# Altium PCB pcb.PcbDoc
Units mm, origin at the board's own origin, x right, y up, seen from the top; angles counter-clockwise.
Board outline 37.4 x 38.1 mm, 2 copper layers (Top Layer, Bottom Layer); 122 components, 90 nets, 413 pads, 142 vias.
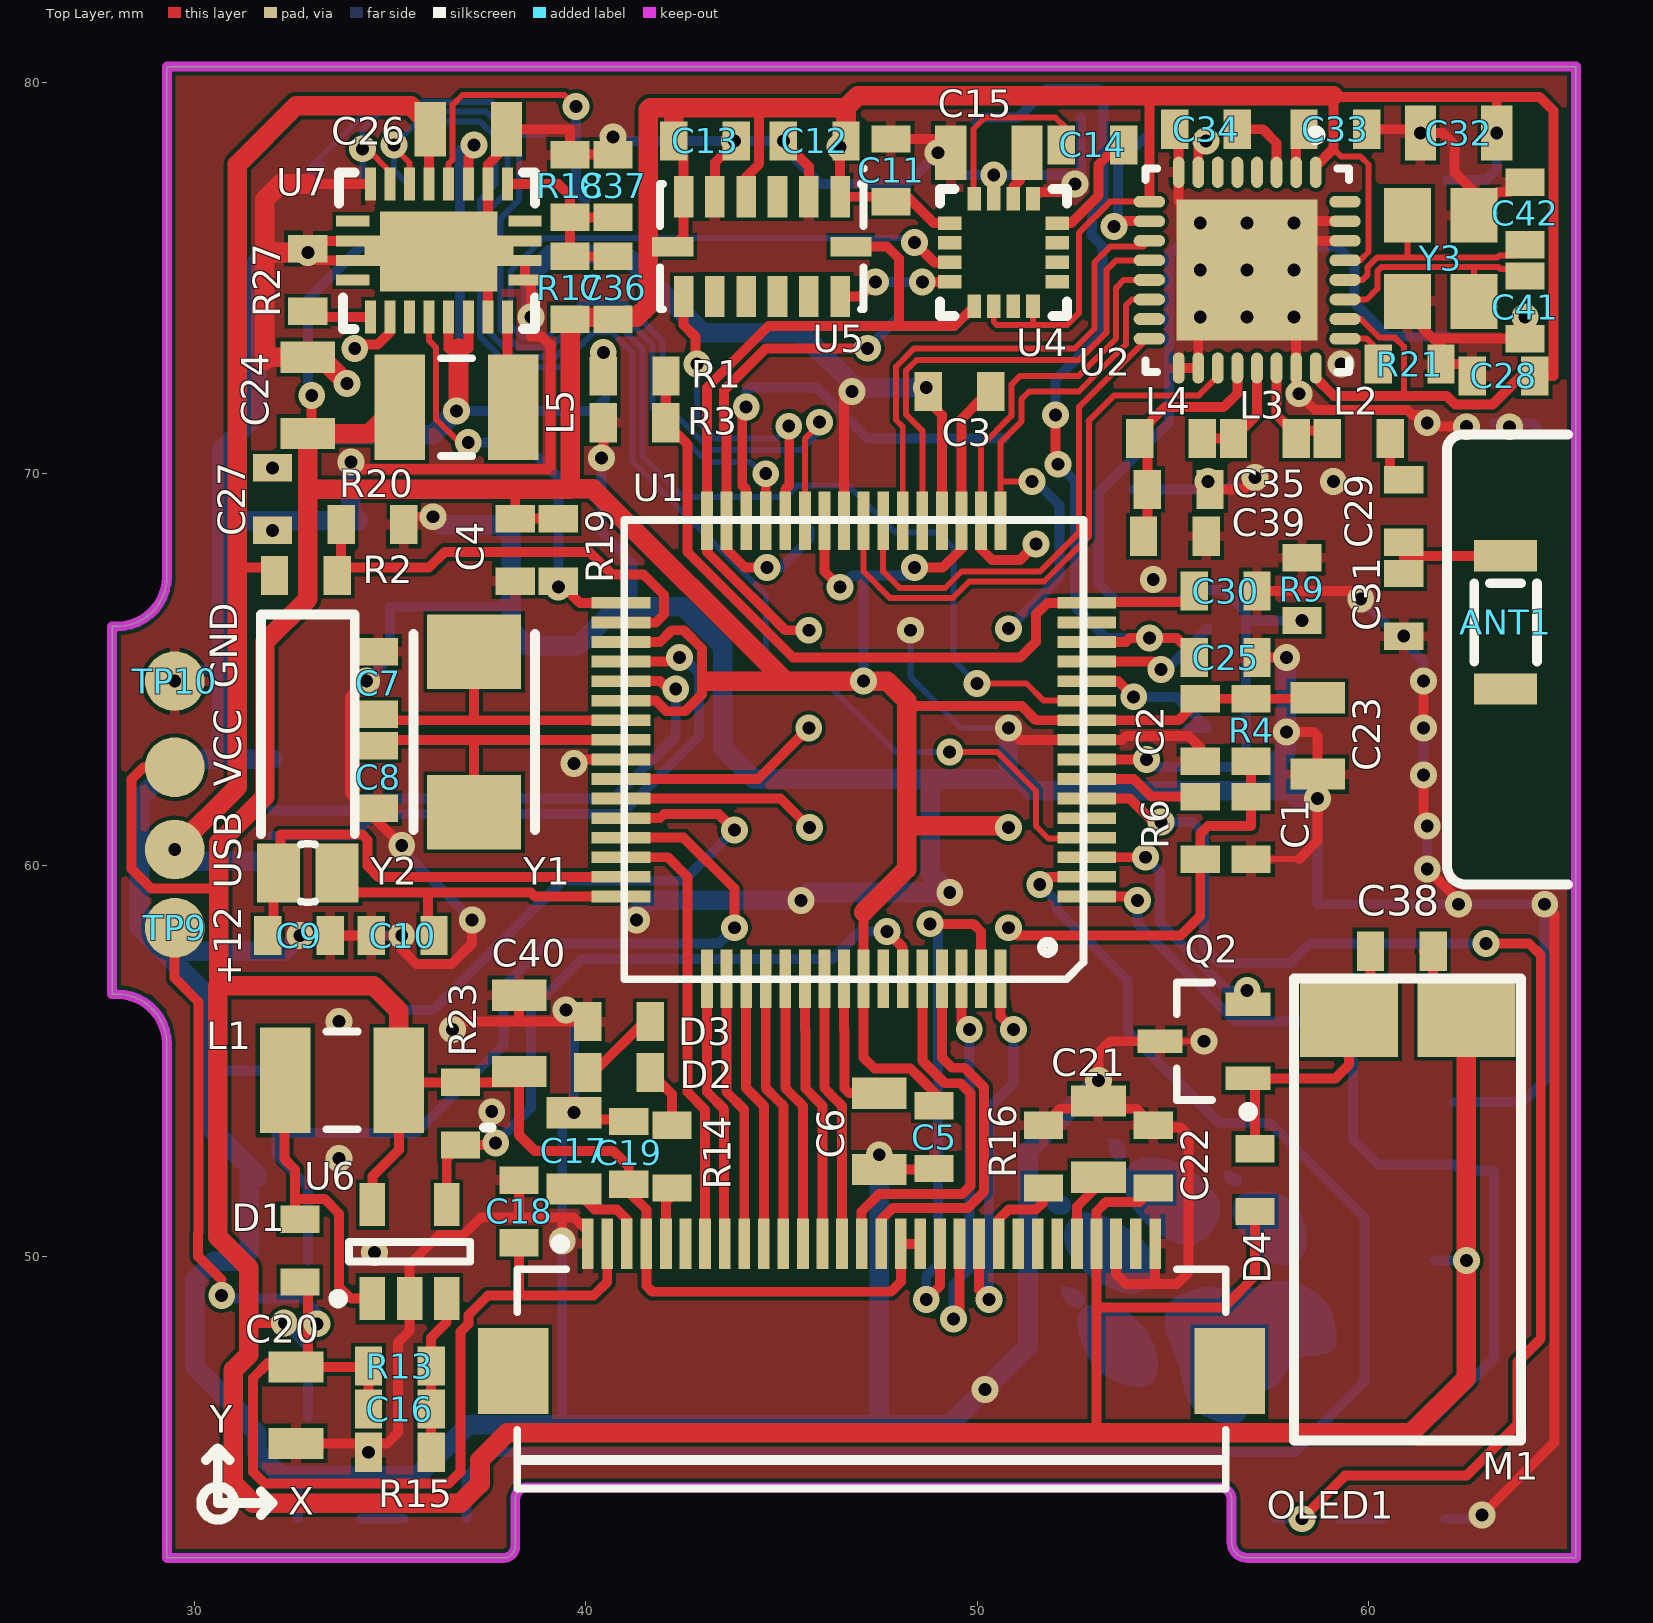
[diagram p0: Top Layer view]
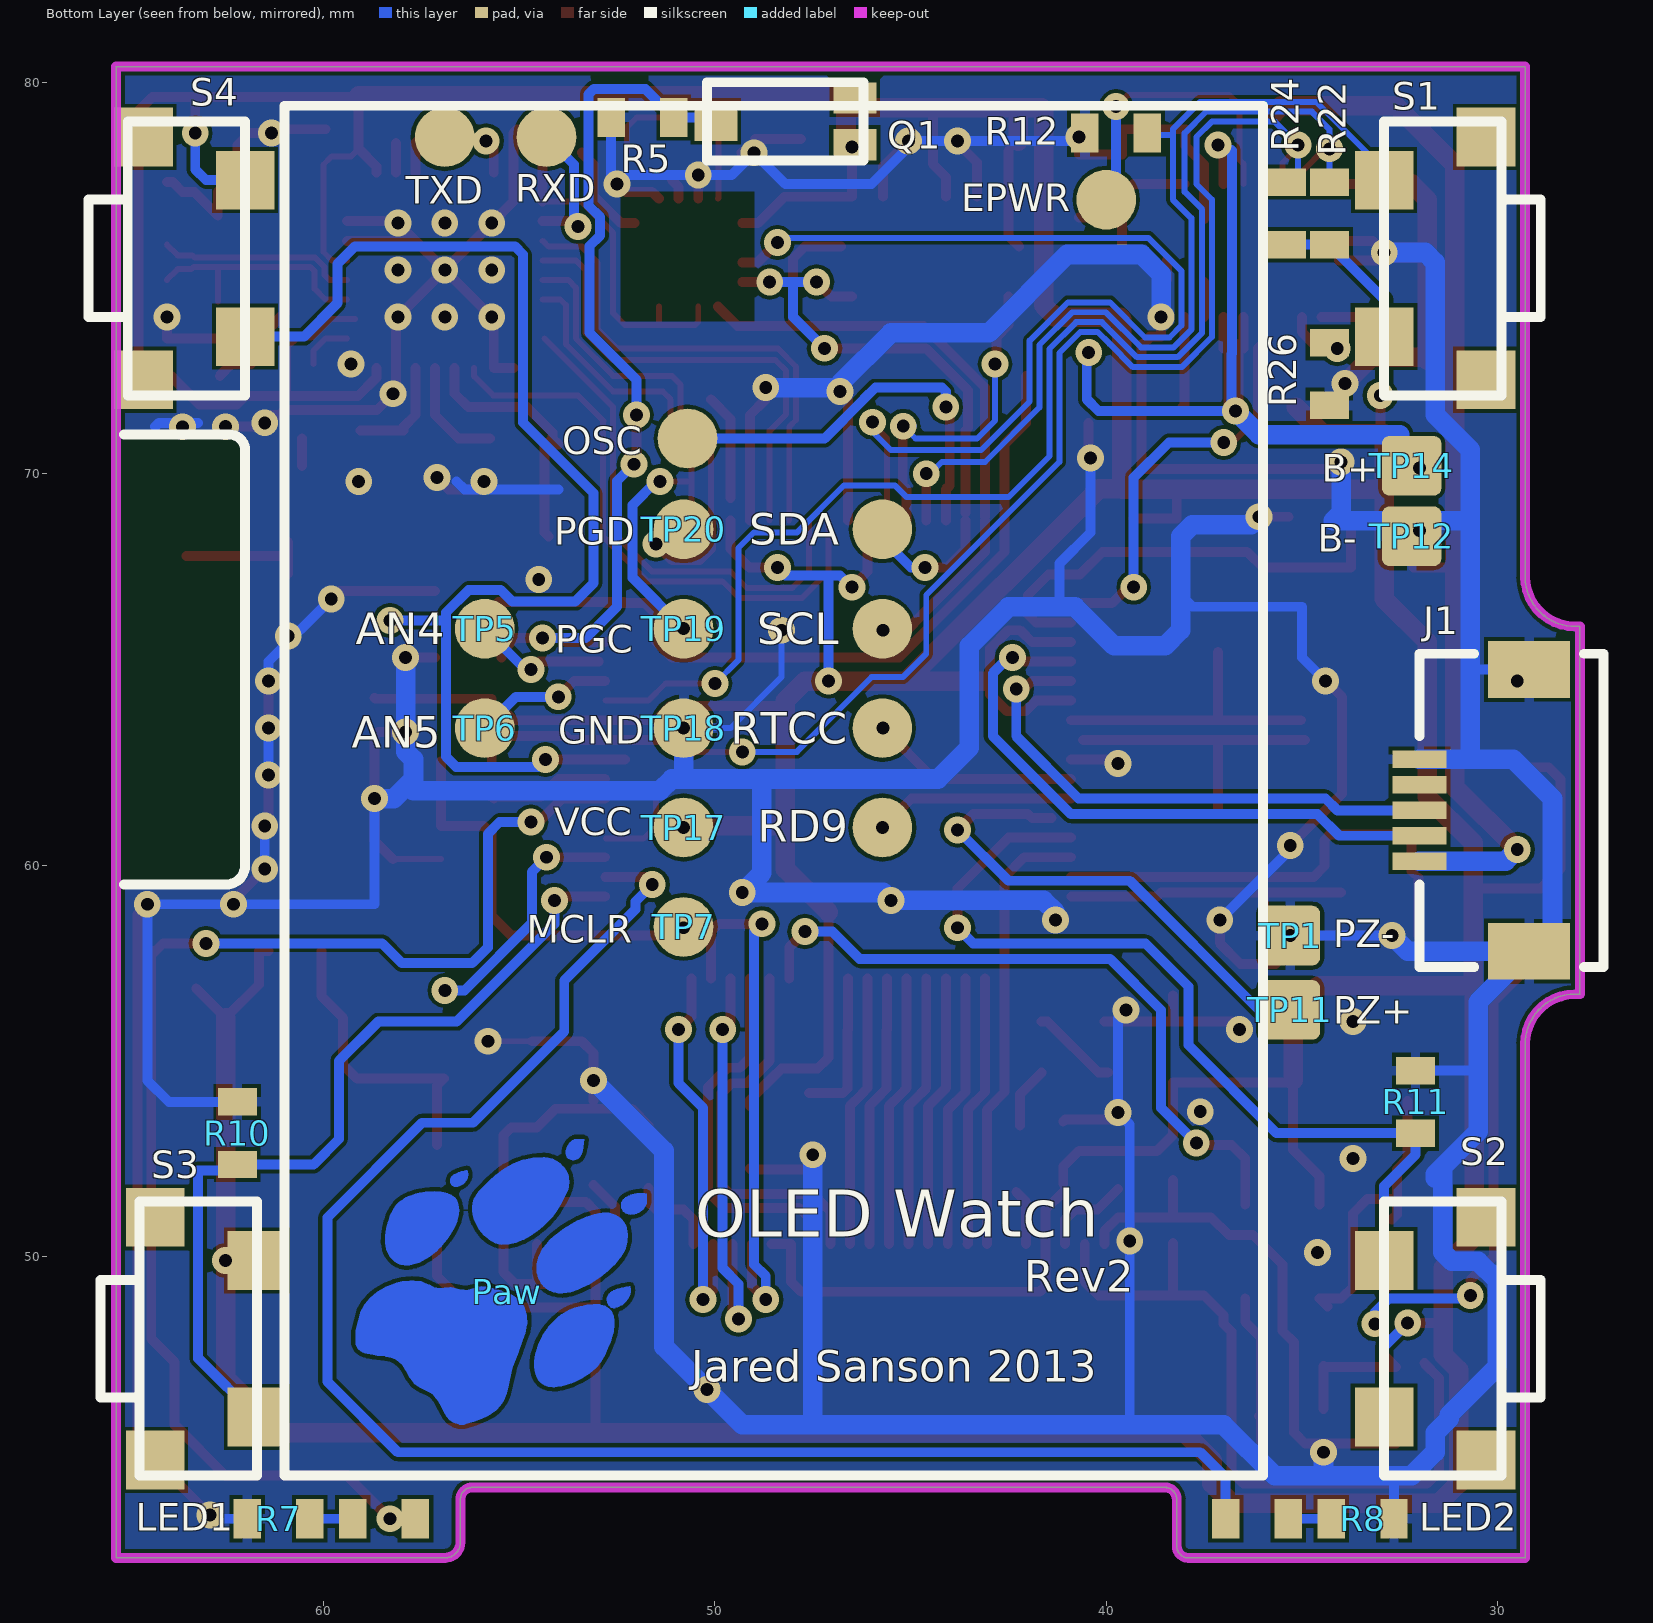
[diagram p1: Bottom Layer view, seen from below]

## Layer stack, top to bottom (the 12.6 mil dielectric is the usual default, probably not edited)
Top Layer: signal copper 0.0356
Dielectric: dielectric 0.32, FR-4, Dk 4.8
Bottom Layer: signal copper 0.0356

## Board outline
56.9,42.3 cw(c56.9,42.7) 56.5,42.7 56.5,43.8 ccw(c56.2,43.8) 56.2,44.1 38.5,44.1 ccw(c38.5,43.8) 38.2,43.8 38.2,42.6 cw(c37.9,42.6) 37.9,42.3 29.3,42.3 29.3,55.43 ccw(c28.03,55.43) 28.03,56.7 27.9,56.7 27.9,66.1 28.03,66.1 ccw(c28.03,67.37) 29.3,67.37 29.3,80.4 65.3,80.4 65.3,42.3

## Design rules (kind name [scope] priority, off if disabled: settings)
Clearance [All] p1: gap=0.1
HoleSize [All] p1: absolutevalues=TRUE maxlimit=2.54 minlimit=0.33 maxpercent=80.000 minpercent=20.000
MaxMinImpedance [InNet('ANT')] p1: minimum=50.00 maximum=50.00
MinimumAnnularRing [All] p1: minimumring=0.178
MinimumSolderMaskSliver [All] p1: minsoldermaskwidth=0
NetAntennae ANT_Antennae [InNet('ANT')] p1: netantennaetolerance=100
NetAntennae [All] p2: netantennaetolerance=0
PolygonConnect PolygonConnect_U2 [All vs (ObjectKind = 'Pad') And (Name = 'U2-33')] p1: connectstyle=Direct reliefconductorwidth=0.254 reliefentries=4 polygonreliefangle="90 Angle"
PolygonConnect PolygonConnect_Via [All vs ObjectKind='Via'] p2: connectstyle=Direct reliefconductorwidth=0.254 reliefentries=4 polygonreliefangle="90 Angle"
PolygonConnect [All] p3: connectstyle=Relief reliefconductorwidth=0.254 reliefentries=4 polygonreliefangle="90 Angle"
RoutingVias [All] p1: holewidth=0.508 width=0.686 viastyle="Through Hole" minholewidth=0.33 minwidth=0.686 maxholewidth=0.711 maxwidth=0.686
SilkscreenOverComponentPads [All] p1: minsilkscreentomaskgap=0.254
SolderMaskExpansion [All] p1: expansion=0.01
Width [All] p1: maxlimit=0.5 minlimit=0.152 preferedwidth=0.254
24 further rules are at their usual default settings.

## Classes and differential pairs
component class sensors: 0.7 C11 C12 C13 C14 C15 C25 Q1 R5 U4 U5
component class power: C24 C26 C27 C36 C37 EPWR J1 L5 R17 R18 R19 R22 R24 R26 R27 TP10 TP12 TP14 U7 U8 USB VCC
component class oled: 0.7 C16 C17 C18 C19 C20 C21 C22 C40 D1 D2 D3 L1 OLED1 R13 R14 R15 R16 R23 TP9 U6
component class cpu: C1 C2 C3 C4 C5 C6 C7 C8 C9 C10 C23 C30 C38 D4 LED1 LED2 M1 OSC Q2 R1 R2 R3 R4 R6 R7 R8 R9 R10 R11 R12 R20 RD9 RTCC S1 S2 S3 S4 SCL SDA TP1 TP5 TP6 TP7 TP11 TP17 TP18 TP19 TP20 U1 Y1 Y2
component class bluetoothle: ANT1 C28 C29 C31 C32 C33 C34 C35 C39 C41 C42 L2 L3 L4 R21 RXD TXD U2 Y3

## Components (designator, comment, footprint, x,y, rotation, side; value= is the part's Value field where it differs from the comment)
ANT1 "2.4GHz Chip Antenna" 2450AT18A100E 63.5,67.9 r270 top
C1 "Cap" 0603C 57,61.6 r270 top
C2 "Cap" 0603C 55.7,64.1 r270 top
C3 "Cap" 0603C 50.2,72.1 r180 top
C4 "Cap" 0603C 38.2,68.7 r270 top
C5 "Cap" 0603C 48.9,53.7 r270 top
C6 "Cap" 0805C 47.5,54.2 r270 top
C7 "Cap" 0603C 34.7,64 r90 top
C8 "Cap" 0603C 34.7,62.9 r270 top
C9 "Cap" 0603C 32.025,58.2 r0 top
C10 "Cap" 0603C 35.975,58.2 r180 top
C11 "Cap" 0603C 47.8,77.1 r90 top
C12 "Cap" 0603C 46.5,78.5 r180 top
C13 "Cap" 0603C 42.4,78.5 r0 top
C14 "Cap" 0603C 52.3,78.4 r0 top
C15 "Cap Pol1" 0805C 51.3,78.2 r180 top
C16 "Cap" 0603C 34.6,46.1 r0 top
C17 "Tantalum" 0805C 39.7,51.7 r90 top
C18 "Cap" 0603C 38.3,50.5 r90 top
C19 "Cap" 0603C 41.1,52 r90 top
C20 "Cap" 0805C 32.6,47.2 r270 top
C21 "Cap" 0805C 53.1,52 r90 top
C22 "Cap" 0603C 54.5,51.9 r90 top
C23 "Cap" 0805C 58.7,64.3 r270 top
C24 "Cap" 0805C 32.9,71 r90 top
C25 "Cap" 0603C 55.7,65.3 r0 top
C26 "Cap" 0805C 36,78.8 r0 top
C27 "Cap" 0603C 32,70 r270 top
C28 "Cap" 0603C 62.8,72.5 r0 top
C29 "Cap" 0603C 60.9,69.7 r270 top
C30 "Cap" 0603C 55.7,67 r0 top
C31 "Cap" 0603C 60.9,66 r90 top
C32 "Cap" 0805C 63.3,78.7 r180 top
C33 "Cap" 0603C 58.5,78.8 r0 top
C34 "Cap" 0603C 56.5,78.8 r180 top
C35 "Cap" 0603C 54.5,69.6 r0 top
C36 "Cap" 0603C 40.7,74.1 r90 top
C37 "Cap" 0603C 40.7,76.7 r90 top
C38 "Cap" 0603C 61.5,57.8 r180 top
C39 "Cap" 0603C 54.4,68.4 r0 top
C40 "Cap" 0805C 38.3,54.7 r90 top
C41 "Cap" 0603C 64,73.6 r90 top
C42 "Cap" 0603C 64,76 r90 top
D1 "MBR0520" 0603D 32.7,50.8 r270 top
D2 "1N4148" 0603D 41.5,54.7 r180 top
D3 "1N4148" 0603D 41.5,56 r180 top
D4 "1N4148" 0603D 57.1,52.6 r270 top
EPWR "AC" TESTPOINT_TOP#1 40,77 r90 bottom (schematic designator TP3)
J1 "MicroUSB" MICRO_USB 32,62.7 r180 bottom
L1 "Inductor" INDC3225N 33.775,54.5 r180 top
L2 "Inductor" 0603L 59.1,70.9 r0 top
L3 "Inductor" 0603L 56.7,70.9 r0 top
L4 "Inductor" 0603L 55.6,70.9 r180 top
L5 "Inductor" INDC3225N 36.7,71.7 r180 top
LED1 "Green" 0603LED 57.8,43.3 r0 bottom
LED2 "Blue" 0603LED 36.8,43.3 r180 bottom
M1 "Vibration Motor" VIBRATION_MOTOR 61,57.3 r270 top
OLED1 "NL128128C OLED" FFC/SM0.5-2H30 47.3,48.7 r0 top
OSC "16MHz" TESTPOINT_TOP#1 50.7,70.9 r90 bottom (schematic designator TP2)
Paw "Comment" PAWPRINT 55.3,49.1 r0 bottom
Q1 "Photo NPN" TEMT6000 46.2,78 r0 bottom
Q2 "MOSFET-N" SOT-23B_N 55.8,55.5 r180 top
R1 "Res3" 0603R 40.6,72.5 r0 top
R2 "Res3" 0603R 33.5,67.4 r180 top
R3 "Res3" 0603R 41.9,71.3 r180 top
R4 "Res3" 0603R 57,64.1 r270 top
R5 "Res3" 0603R 51.2,79.1 r0 bottom
R6 "Res3" 0603R 55.7,60.3 r90 top
R7 "Res3" 0603R 61.8,43.3 r180 bottom
R8 "Res3" 0603R 32.8,43.3 r0 bottom
R9 "Res3" 0603R 58.3,66.4 r90 top
R10 "Res3" 0603R 62.2,52.5 r90 bottom
R11 "Res3" 0603R 32.1,53.3 r90 bottom
R12 "Res3" 0603R 39.1,78.7 r0 bottom
R13 "Res3" 0603R 35.9,47.2 r180 top
R14 "Res3" 0603R 42.2,53.2 r270 top
R15 "Res3" 0603R 34.6,45 r0 top
R16 "Res3" 0603R 51.7,51.9 r90 top
R17 "Res3" 0603R 39.6,74.1 r90 top
R18 "Res3" 0603R 39.6,76.7 r90 top
R19 "Res3" 0603R 39.3,68.7 r270 top
R20 "Res3" 0603R 35.2,68.7 r180 top
R21 "Res3" 0603R 61.7,72.8 r180 top
R22 "Res3" 0603R 34.3,76 r90 bottom
R23 "Res3" 0603R 36.8,53 r90 top
R24 "Res3" 0603R 35.4,76 r90 bottom
R26 "Res3" 0603R 34.3,73.2 r270 bottom
R27 "Res3" 0603R 32.9,74.3 r90 top
RD9 "" TESTPOINT_TOP#1 45.72,60.96 r90 bottom (schematic designator TP2)
RTCC "RTCC" TESTPOINT_TOP#1 45.72,63.5 r90 bottom (schematic designator TP8)
RXD "AN4" TESTPOINT_TOP#1 54.3,78.6 r90 bottom (schematic designator TP4)
S1 "SideButton" SIDE_BUTTON 32.9,79 r180 bottom
S2 "SideButton" SIDE_BUTTON 32.9,51.4 r180 bottom
S3 "SideButton" SIDE_BUTTON 61.7,44.4 r0 bottom
S4 "SideButton" SIDE_BUTTON 62,72 r0 bottom
SCL "SCL" TESTPOINT_TOP#1 45.72,66.04 r90 bottom (schematic designator TP3)
SDA "SDA" TESTPOINT_TOP#1 45.72,68.58 r90 bottom (schematic designator TP2)
TP1 "PZ-" TESTPOINT_TOP#2 35.3,58.2 r180 bottom
TP5 "AN4" TESTPOINT_TOP#1 55.88,66.04 r90 bottom
TP6 "AN5" TESTPOINT_TOP#1 55.88,63.5 r90 bottom
TP7 "MCLR" TESTPOINT_TOP#1 50.8,58.42 r90 bottom
TP9 "+12" TESTPOINT_TOP#1 29.5,58.4 r90 top
TP10 "GND" TESTPOINT_TOP#1 29.5,64.7 r90 top
TP11 "PZ+" TESTPOINT_TOP#2 35.3,56.3 r90 bottom
TP12 "B-" TESTPOINT_TOP#2 32.2,68.4 r90 bottom
TP14 "B+" TESTPOINT_TOP#2 32.2,70.2 r90 bottom
TP17 "VCC" TESTPOINT_TOP#1 50.8,60.96 r0 bottom
TP18 "GND" TESTPOINT_TOP#1 50.8,63.5 r0 bottom
TP19 "PGC" TESTPOINT_TOP#1 50.8,66.04 r0 bottom
TP20 "PGD" TESTPOINT_TOP#1 50.8,68.58 r90 bottom
TXD "AN4" TESTPOINT_TOP#1 56.9,78.6 r90 bottom (schematic designator TP3)
U1 "PIC24FJ128GB206" TQFP_64_10MM 54,59.2 r180 top
U2 "nRF8001" QFN50P500X500-32V5N 56.9,75.2 r270 top
U4 "HMC5883L" HMC5883L_16PINQFN 49.3,74.9 r90 top
U5 "MMA7455LR1" LGA80P500X300-14N 44.5,75.8 r270 top
U6 "LM27313XMF" MF05A_N 35.5,50.125 r90 top
U7 "BQ25010" RHL 38,77.4 r180 top
USB "VBUS" TESTPOINT_TOP#1 29.5,60.4 r90 top (schematic designator TP8)
VCC "VCC" TESTPOINT_TOP#1 29.5,62.5 r90 top (schematic designator TP4)
Y1 "32MHz" ABRACON32MHZ 37.2,65.5 r270 top
Y2 "32.768kHz" BCY-W2/D1.5 32.9,59.8 r270 top
Y3 "TXC-16MHz" TXC-16MHZ 62.7,76.6 r270 top

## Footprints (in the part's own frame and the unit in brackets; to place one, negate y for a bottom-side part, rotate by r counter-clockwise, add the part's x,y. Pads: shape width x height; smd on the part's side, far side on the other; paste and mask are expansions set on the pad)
0603C [mm] "0603 (1608 metric) Capacitor Footprint"
  rect 0.7x1 smd mask+0.01: 1(-0.15,0) 2(1.45,0)
  body extent -0.15,-0.4 1.45,0.4, height 0.8
0603D [mm] "0603 (1608 metric) Diode Footprint"
  rect 0.7x1 smd mask+0.01: 1(-0.15,0) 2(1.45,0)
  body extent -0.12,-0.4 1.43,0.4, height 0.63
0603L [mm] "0603 (1608 metric) Inductor Footprint"
  rect 0.7x1 smd mask+0.01: 1(-0.15,0) 2(1.45,0)
  body extent -0.15,-0.4 1.45,0.4, height 0.8
0603LED [mm] "0603 (1608 metric) LED Footprint"
  rect 0.7x1 smd mask+0.01: 1(-0.15,0) 2(1.45,0)
  body extent -0.12,-0.37 1.43,0.38, height 0.55
0603R [mm] "0603 (1608 metric) Resistor Footprint"
  rect 0.7x1 smd mask+0.01: 1(-0.15,0) 2(1.45,0)
  body extent -0.15,-0.4 1.45,0.4, height 0.45
0805C [mm] "0805 (2012 metric) Capacitor Footprint"
  rect 0.8x1.4 smd mask+0.01: 1(0.025,0) 2(1.975,0)
  body extent 0,-0.63 2,0.63, height 1.1
2450AT18A100E [mm] "2.4GHz Chip Antenna"
  rect 0.8x1.6 smd: 1(0,0) 2(3.4,0)
  silkscreen extent 0.7,-0.8 2.7,0.8, body extent 0.1,-0.8 3.3,0.8, height 1.33
ABRACON32MHZ [mm] "ABRACON 32MHz SMD Crystal"
  rect 1.9x2.4 smd: 1(0.05,-0.05) 2(4.15,-0.05)
  silkscreen extent -0.4,-1.6 4.6,1.5, body extent -0.4,-1.65 4.6,1.55, height 1.3
BCY-W2/D1.5 [mm] "Crystal, Thru-Hole; 2 Leads; Body 1.5 x 5.1 mm (Dia.xH)"
  rect 1.5x1.1 smd: 1(0,0.75) 2(0,-0.75)
  silkscreen extent -0.75,-0.18 0.75,0.18
FFC/SM0.5-2H30 [mm] "Connector; FH12 Series; 30 Position; 0.5mm Spaced Bottom Contact"
  rect 0.3x1.3 smd: 1(-7.25,1.625) 2(-6.75,1.625) 3(-6.25,1.625) 4(-5.75,1.625) 5(-5.25,1.625) 6(-4.75,1.625) 7(-4.25,1.625) 8(-3.75,1.625) 9(-3.25,1.625) 10(-2.75,1.625) 11(-2.25,1.625) 12(-1.75,1.625) 13(-1.25,1.625) 14(-0.75,1.625) 15(-0.25,1.625) 16(0.25,1.625) 17(0.75,1.625) 18(1.25,1.625) 19(1.75,1.625) 20(2.25,1.625) 21(2.75,1.625) 22(3.25,1.625) 23(3.75,1.625) 24(4.25,1.625) 25(4.75,1.625) 26(5.25,1.625) 27(5.75,1.625) 28(6.25,1.625) 29(6.75,1.625) 30(7.25,1.625)
  rect 1.8x2.2 smd: 31(-9.15,-1.625) 32(9.15,-1.625)
  silkscreen extent -9.05,-4.62 9.05,1.75, body extent -9.05,-4.62 9.05,0.97, height 2
HMC5883L_16PINQFN [mm]
  rect 0.6x0.35 smd: 1(-0.625,-0.625) 2(-0.625,-1.125) 3(-0.625,-1.625) 4(-0.625,-2.125) 9(2.125,-2.125) 10(2.125,-1.625) 11(2.125,-1.125) 12(2.125,-0.625)
  rect 0.35x0.6 smd: 5(0,-2.75) 6(0.5,-2.75) 7(1,-2.75) 8(1.5,-2.75) 13(1.5,0) 14(1,0) 15(0.5,0) 16(0,0)
  silkscreen extent -0.87,-3 2.37,0.25, body extent -0.75,-2.87 2.25,0.13, height 0.9
INDC3225N [mm] "Chip Inductor, Body 3.2x2.5mm, IPC Medium Density"
  rect 1.3x2.7 smd: 1(-1.45,0) 2(1.45,0)
  silkscreen extent -0.4,-1.25 0.4,1.25, body extent -1.7,-1.35 1.7,1.35, height 1.5
LGA80P500X300-14N [mm] "LGA, 14-Leads, Body 3x5x0.92mm, Pitch 0.8mm, IPC Medium Density"
  rect 1.05x0.5 smd: 1(-1.275,2) 2(-1.275,1.2) 3(-1.275,0.4) 4(-1.275,-0.4) 5(-1.275,-1.2) 6(-1.275,-2) 8(1.275,-2) 9(1.275,-1.2) 10(1.275,-0.4) 11(1.275,0.4) 12(1.275,1.2) 13(1.275,2)
  rect 0.5x1.05 smd: 7(0,-2.275) 14(0,2.275)
  silkscreen extent -2.05,-2.6 1.6,2.65, body extent -1.57,-2.57 1.58,2.58, height 1
MF05A_N [mm] "SOT23, 5-Leads, Body 2.9x1.6mm, Pitch 0.95mm, Lead Span 2.8mm, IPC Medium Density"
  rect 1.1x0.65 smd: 1(-1.2,0.95) 2(-1.2,0) 3(-1.2,-0.95) 4(1.2,-0.95) 5(1.2,0.95)
  silkscreen extent -1.32,-1.55 0.25,1.95, body extent -0.9,-1.55 0.9,1.55, height 1.19
MICRO_USB [mm] "Micro USB Connector"
  rect 1.38x0.45 smd: 1(0,-2.6) 2(0,-1.95) 3(0,-1.3) 4(0,-0.65) 5(0,0)
  rect 2.1x1.45 smd: 5(2.8,-4.9) 5(2.8,2.3)
  silkscreen extent 0,-5.3 4.7,2.7, body extent 0.05,-5.29 5.48,2.69, height 2.69
PAWPRINT [mm] "Wolf Paw"
  Top Layer drawing of 732 lines, arcs and shapes, not listed
QFN50P500X500-32V5N [mm] "QFN, 32-Leads, Body 5x5mm, Pitch 0.5mm, IPC Medium Density"
  oval 0.8x0.3 smd: 1(-2.5,1.75) 2(-2.5,1.25) 3(-2.5,0.75) 4(-2.5,0.25) 5(-2.5,-0.25) 6(-2.5,-0.75) 7(-2.5,-1.25) 8(-2.5,-1.75) 17(2.5,-1.75) 18(2.5,-1.25) 19(2.5,-0.75) 20(2.5,-0.25) 21(2.5,0.25) 22(2.5,0.75) 23(2.5,1.25) 24(2.5,1.75)
  oval 0.3x0.8 smd: 9(-1.75,-2.5) 10(-1.25,-2.5) 11(-0.75,-2.5) 12(-0.25,-2.5) 13(0.25,-2.5) 14(0.75,-2.5) 15(1.25,-2.5) 16(1.75,-2.5) 25(1.75,2.5) 26(1.25,2.5) 27(0.75,2.5) 28(0.25,2.5) 29(-0.25,2.5) 30(-0.75,2.5) 31(-1.25,2.5) 32(-1.75,2.5)
  rect 3.6x3.6 smd: 33(0,0)
  silkscreen extent -3.57,-2.6 2.6,2.6, body extent -2.58,-2.58 2.58,2.58, height 1
RHL [mm]
  rect 0.85x0.28 smd mask+0.07: 0(-0.45,1.95) 0(-0.45,1.45) 0(3.95,1.45) 0(3.95,1.95) 1(-0.45,0.95) 10(3.95,0.95) 11(3.95,2.45) 20(-0.45,2.45)
  rect 0.4x0.78 smd mask+0.07: 0(0.05,1.7) 0(3.45,1.7)
  rect 3x2.05 smd mask+0.07: 0(1.75,1.725)
  rect 0.28x0.85 smd mask+0.07: 2(0,0) 3(0.5,0) 4(1,0) 5(1.5,0) 6(2,0) 7(2.5,0) 8(3,0) 9(3.5,0) 12(3.5,3.4) 13(3,3.4) 14(2.5,3.4) 15(2,3.4) 16(1.5,3.4) 17(1,3.4) 18(0.5,3.4) 19(0,3.4)
  silkscreen extent -0.7,-0.3 4.3,3.7, body extent -0.52,-0.12 4.13,3.53, height 1
SIDE_BUTTON [mm] "SMD Button Side Activated"
  rect 1.5x1.5 smd: 1(0,-1.5) 2(0,-5.5) 3(2.6,-6.6) 3(2.6,-0.4)
  silkscreen extent 0,-7 4,0, body extent 0,-7 4,0, height 3.5
SOT-23B_N [mm] "SOT23, 3-Leads, Body 2.9x1.3mm, Pitch 0.95mm, Lead Span 2.4mm, IPC Medium Density"
  rect 1.15x0.6 smd: 1(-1.125,0.95) 2(-1.125,-0.95) 3(1.125,0)
  silkscreen extent -1.25,-1.5 0.7,1.92, body extent -0.7,-1.5 0.7,1.5, height 1.14
TEMT6000 [mm] "Ambient Light Sensor"
  rect 1.1x0.8 smd: 1(0.225,-0.4) 2(0.225,-1.6)
  rect 1.1x1 smd: 3(3.775,-1)
  silkscreen extent 0,-2 4,0, body extent 0,-2 4,0, height 1.05
TESTPOINT_TOP#1 [mil] "Test Point Pad"
  round 60 smd: 1(0,0)
TESTPOINT_TOP#2 [mil] "Test Point Pad"
  rrect25% 60x60 smd: 1(0,0)
TQFP_64_10MM [mm]
  rect 1.5x0.3 smd: 1(1.2,0) 2(1.2,-0.5) 3(1.2,-1) 4(1.2,-1.5) 5(1.2,-2) 6(1.2,-2.5) 7(1.2,-3) 8(1.2,-3.5) 9(1.2,-4) 10(1.2,-4.5) 11(1.2,-5) 12(1.2,-5.5) 13(1.2,-6) 14(1.2,-6.5) 15(1.2,-7) 16(1.2,-7.5) 33(13.1,-7.5) 34(13.1,-7) 35(13.1,-6.5) 36(13.1,-6) 37(13.1,-5.5) 38(13.1,-5) 39(13.1,-4.5) 40(13.1,-4) 41(13.1,-3.5) 42(13.1,-3) 43(13.1,-2.5) 44(13.1,-2) 45(13.1,-1.5) 46(13.1,-1) 47(13.1,-0.5) 48(13.1,0)
  rect 0.3x1.5 smd: 17(3.4,-9.6) 18(3.9,-9.6) 19(4.4,-9.6) 20(4.9,-9.6) 21(5.4,-9.6) 22(5.9,-9.6) 23(6.4,-9.6) 24(6.9,-9.6) 25(7.4,-9.6) 26(7.9,-9.6) 27(8.4,-9.6) 28(8.9,-9.6) 29(9.4,-9.6) 30(9.9,-9.6) 31(10.4,-9.6) 32(10.9,-9.6) 49(10.9,2.1) 50(10.4,2.1) 51(9.9,2.1) 52(9.4,2.1) 53(8.9,2.1) 54(8.4,2.1) 55(7.9,2.1) 56(7.4,2.1) 57(6.9,2.1) 58(6.4,2.1) 59(5.9,2.1) 60(5.4,2.1) 61(4.9,2.1) 62(4.4,2.1) 63(3.9,2.1) 64(3.4,2.1)
  silkscreen extent 1.28,-9.61 13.01,2.12, body extent 2.5,-8.5 12,1, height 2
TXC-16MHZ [mm]
  rect 1.4x1.2 smd: 1(0,-1.7) 2(2.2,-1.7) 3(2.2,0) 4(0,0)
  body extent -0.6,-2.2 2.8,0.5, height 0.7
VIBRATION_MOTOR [mm]
  rect 2x2.5 smd: 1(1.2,1.5) 2(1.2,-1.5)
  silkscreen extent 0.2,-2.9 12,2.9, body extent 0.6,-2.5 11.5,2.5, height 5

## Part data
ANT1: library part 2450AT18A100E
C1 C2 C3 C4 C5 C6 C7 C8 C9 C10 C11 C12 C13 C14 C16 C18 C19 C20 C21 C22 C23 C24 C25 C26 C27 C28 C29 C30 C31 C32 C33 C34 C35 C36 C37 C38 C39 C40 C41 C42: "Capacitor"
C15: "Polarized Capacitor (Radial)"
C17: library part "Cap Pol1", "Polarized Capacitor (Radial)"
D1: library part "D Schottky", "Schottky Diode"
D2 D3 D4: library part Diode, "Default Diode"
EPWR OSC RD9 RTCC RXD SCL SDA TP1 TP5 TP6 TP7 TP9 TP10 TP11 TP12 TP14 TP17 TP18 TP19 TP20 TXD USB VCC: library part TestPoint, "Test Point"
LED1 LED2: library part LED2, "Typical RED, GREEN, YELLOW, AMBER GaAs LED"
M1: library part VibrationMotor
OLED1: library part NL128128C, "128x128 OLED Display"
Q1: "NPN Phototransistor"
Q2: "N-Channel MOSFET"
R1 R2 R3 R4 R5 R6 R7 R8 R9 R10 R11 R12 R13 R14 R15 R16 R17 R18 R19 R20 R21 R22 R23 R24 R26 R27: "Resistor"
U4: "Honeywell 3 Axis Magnetometer"
U5: "3-Axis Accelerometer, 5g"
U6: "1.6 MHz Boost Converter With 30V Internal FET Switch in SOT-23"
Y1 Y2: library part XTAL, "Crystal Oscillator"
Y3: library part CrystalTXC

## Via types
v1: diameter 0.686, hole 0.33, Top Layer to Bottom Layer, tented both sides, 142 vias

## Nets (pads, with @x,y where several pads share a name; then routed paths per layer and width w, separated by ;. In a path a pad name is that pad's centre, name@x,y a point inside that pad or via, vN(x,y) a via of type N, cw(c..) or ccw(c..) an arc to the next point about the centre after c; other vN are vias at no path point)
+12: C16.1 C18.1 C20.1 D1.2 OLED1.2 R13.2 TP9.1 | length 36.5
  Top Layer w0.254: TP9.1 29.5,57.112 30.112,56.5 30.112,50.612 30.1,50.6 30.1,50 30.7,49.4 ; 31.875,47.275 31.5,46.9 31.5,44.5 31.8,44.2 36.5,44.2 36.8,44.5 36.8,48.079 37.002,48.281 37.002,48.502 37.5,49 38.3,49 ; D1.2 32.9,49.15 32.9,47.475 C20.1 34.425,47.175 R13.2 C16.1 ; C18.1 38.3,49 ; OLED1.2 40.55,49.35 40.2,49 38.3,49
  Bottom Layer w0.254: v1@30.7,48.923 32.788,48.923 33.131,48.58 v1(33.131,48.281)
  other v1: 30.7,49
AN3: TP5.1 U1.13 | length 3.5
  Top Layer w0.254: U1.13@52.966,65.2 54.5,65.2 v1(54.7,65)
  Bottom Layer w0.254: v1(54.7,65) 54.84,65 TP5.1 TP5.1@55.88,65.98
AN4: TP6.1 U1.12 | length 4.1
  Top Layer w0.254: U1.12 53.6,64.7 v1(54,64.3)
  Bottom Layer w0.254: v1(54,64.3) 55.08,64.3 TP6.1 TP6.1@55.4,63.5
AN_LIGHT: C25.1 Q1.3 R5.1 U1.14 | length 23
  Top Layer w0.254: v1(52.07,70.242) 52,70.312 v1(52,71.5) v1@52.07,71.43 ; U1.14 53.8,65.7 53.9,65.8 v1(54.4,65.8) 55.1,65.8 55.45,65.45 C25.1@55.45,65.3
  Bottom Layer w0.254: Q1.3 50.075,79.1 R5.1 51.777,79.827 53.094,79.827 53.227,79.694 53.227,76.852 52.93,76.555 52.93,76.083 53.2,75.813 53.2,73.6 52,72.4 v1(52,71.5) ; v1(52.07,70.242) 52.5,69.812 52.5,66.6 53.3,65.8 v1(54.4,65.8)
AN_TEMP: U1.15
ANT: ANT1.1 C29.2 C31.2 | length 3.4
  Top Layer w0.254: C31.2 60.9,67.85 ; C29.2 60.9,67.85 ; ANT1.1 60.95,67.9 60.9,67.85
ANT1: L3.1 L4.1 U2.21 | length 2.8
  Top Layer w0.254: L4.1 L3.1 57.15,71.5 U2.21
ANT2: L2.1 L3.2 U2.22 | length 2.7
  Top Layer w0.254: U2.22 57.65,71.5 L3.2@57.95,71.2 ; L3.2@57.95,71.1 L2.1@59.05,71.1
BT_IREF: R21.2 U2.25 | length 1.3
  Top Layer w0.152: U2.25 59.95,73.45 60.25,73.15 R21.2
BT_RDYN: U1.23 U2.16 | length 12.7
  Top Layer w0.152: U1.23 47.6,67.5 48.019,67.081 49.181,67.081 49.6,67.5 49.603,67.497 51.603,67.497 52.6,68.494 52.6,71.243 52.598,71.245 52.598,71.455 52.6,71.457 52.6,71.7 U2.16@54.35,73.45
BT_REQN: U1.21 U2.12 | length 12.3
  Top Layer w0.152: U1.21 48.6,71.1 48.181,71.519 48.181,72.63 48.451,72.9 52.6,72.9 53.3,73.6 53.3,75.2 53.55,75.45 U2.12
BTN1: R12.1 S1.1 U1.29 | length 24.3
  Top Layer w0.254: U1.29 v1(44.6,70)
  Bottom Layer w0.152: S1.1 32.9,77.757 34.643,79.5 37.6,79.5 38.3,78.8 38.3,78.648 ; R12.1 38.898,78.648 38.3,78.648 ; v1(44.6,70) 44.5,70 44.2,70.3 43.1,70.3 41.705,71.695 41.705,73.293 40.874,74.124 40.01,74.124 39.115,73.228 38.28,73.228 37.828,73.68 37.828,76.528 38.3,77 38.3,78.648
  Bottom Layer w0.254: S1.1 S1.1@33.25,77.85
BTN2: R11.1 S2.1 U1.45 | length 22.8
  Top Layer w0.254: U1.45 42.5,60.7 43.8,59.4 v1(43.8,58.4)
  Bottom Layer w0.254: S2.1 32.9,51.8 32.1,52.6 R11.1 35.65,53.15 37.9,55.4 37.9,56.9 39,58 43.4,58 v1(43.8,58.4)
BTN3: R10.1 S3.1 U1.1 | length 21.6
  Top Layer w0.254: U1.1 v1@54,59.2
  Bottom Layer w0.254: v1(54.1,59.1) 54.1,58.5 56.6,56 58.6,56 59.6,55 59.6,53 60.25,52.35 R10.1 62.35,52.2 63.2,52.2 63.2,47.4 S3.1
BTN4: R9.1 S4.1 U1.8 | length 31.8
  Top Layer w0.254: U1.8@52.3,62.7 U1.8 v1@54,62.7
  Bottom Layer w0.254: v1(54.329,62.7) 54.518,62.511 56.611,62.511 56.869,62.769 56.869,66.2 ; v1(58.3,66.25) 56.919,66.25 56.869,66.2 ; S4.1 60.5,73.5 59.646,74.354 59.646,75.354 59.2,75.8 55.1,75.8 54.9,75.6 54.9,71.306 53.1,69.506 53.1,67.2 53.57,66.73 55.171,66.73 55.47,67.029 56.29,67.029 56.869,66.45 56.869,66.2
D+: J1.3 U1.37 | length 13.8
  Top Layer w0.254: U1.37 41.9,64.7 v1@42.1,64.5
  Bottom Layer w0.254: J1.3 34.1,61.4 34.4,61.7 40.706,61.7 42.3,63.294 v1(42.3,64.5) v1@42.1,64.5
D-: J1.2 U1.36 | length 15.9
  Top Layer w0.254: U1.36 42.1,65.2 v1@42.2,65.3
  Bottom Layer w0.254: J1.2 34.05,60.75 34.6,61.3 40.9,61.3 42.9,63.3 42.9,64.9 42.35,65.45 v1@42.2,65.3
  other v1: 42.4,65.3
DEC1: C33.1 U2.2 | length 0.8
  Top Layer w0.254: U2.2 C33.1@58.15,78.45
DEC2: C34.1 U2.3 | length 1.9
  Top Layer w0.254: C34.1 57.3,78.8 57.65,78.45 U2.3
FB: C16.2 R13.1 R15.2 U6.3 | length 4.1
  Top Layer w0.254: C16.2@36,45.925 36.05,45.875 R15.2 ; C16.2@36.1,45.925 36.05,45.975 36.05,47.925 36.45,48.325 U6.3
GND: C1.2 C2.2 C3.2 C4.2 C5.2 C6.2 C7.2 C8.2 C9.2 C10.2 C11.2 C12.2 C13.2 C15.2 C17.2 C18.2 C19.2 C20.2 C21.2 C22.2 C23.2 C24.2 C25.2 C26.2 C27.2 C28.1 C30.2 C31.1 C32.2 C33.2 C34.2 C35.2 C37.2 C39.2 C40.2 C41.1 C42.2 D3.2 J1.5 OLED1.1 OLED1.28 OLED1.30 Q2.3 R3.2 R5.2 R7.1 R8.1 R9.2 R10.2 R11.2 R12.2 R15.1 R16.2 R18.2 R20.1 R21.1 R26.2 R27.2 TP1.1 TP10.1 TP12.1 TP18.1 U1.9 U1.20 U1.25 U1.41 U2.8 U2.17 U2.18 U2.23 U2.30 U2.31 U2.33 U4.9 U4.11 U5.2 U5.5 U6.2 U7.0 U7.3 U7.9 U7.18 U7.20 Y3.2 Y3.4 | length 380.1
  Top Layer w0.152: Q2.3 v1(55.8,55.5) ; C1.2 58.225,60.15
  Top Layer w0.254: C20.2 34.925,45.225 35.2,45.5 35.2,47.8 35.5,48.1 U6.2 35.5,49.8 36.248,50.548 36.869,50.548 37.321,51 38.3,51 39.4,51 ; v1(32.7,58.2) C9.2 ; R27.2 v1(32.9,75.65) ; 32.9,77.4 U7.9 ; C9.2@33.575,58.2 C10.2@34.425,58.2 ; v1@33.623,56.077 v1(33.7,56) ; v1(34,70.3) 34.177,70.123 39.023,70.123 39.1,70.2 39.1,73.3 39.079,73.3 38.879,73.5 38.6,73.5 v1(38.6,74) 38.6,74.8 U7.20 U7.0@38.45,75.45 ; U7.0@34.05,75.45 33.1,75.45 v1(32.9,75.65) ; U7.0@34.05,75.95 33.2,75.95 v1(32.9,75.65) ; v1(34.4,64.7) 34.379,64.7 33.973,64.294 33.973,61.827 v1(35.3,60.5) ; v1(35.3,58.2) 35.3,57.854 35.681,57.473 36.569,57.473 37.1,58.004 v1(37.1,58.6) ; R20.1@35.35,68.9 v1(36.1,68.9) ; v1(36.6,55.8) 36.8,56 D3.2 ; U7.18 U7.0@37.5,74.9 ; U7.0@37.5,76.5 U7.3 37.5,77.9 37.975,78.375 C26.2 39.6,78.8 R18.2 C37.2 ; 38.3,51 C18.2 ; 38.3,56 C40.2 ; v1(39.4,50.4) 39.4,51 ; v1(39.7,53.675) 39.875,53.5 41.05,53.5 C19.2 ; v1(39.7,62.6) 39.8,62.7 U1.41 ; OLED1.1 40.05,50.65 39.7,51 39.4,51 ; v1(40.4,70.4) 40.45,70.45 R3.2 ; C37.2 v1(40.7,78.6) ; U5.5 43.3,77.95 C13.2 ; v1(45.05,78.5) 45.7,77.85 U5.2 ; U1.25 46.6,71.9 v1(46.8,72.1) ; C6.2 v1(47.5,52.6) ; C6.2@47.6,52.225 49.075,52.225 C5.2@49.1,52.25 ; C11.2 C15.2@48.975,78.55 ; v1(48.7,72.2) 48.7,71.9 49.1,71.5 49.1,70.1 U1.20 ; v1(49,78.2) C15.2 ; U4.11 v1(50.425,77.626) ; v1(50.8,63.5) 51.1,63.2 U1.9 53.7,63.2 53.8,63.3 55.4,63.3 55.7,63 C2.2 ; U4.9 51.6,77.2 v1@52.273,77.2 ; R16.2 52.125,53.775 54.075,53.775 C22.2 54.55,53.3 55.2,53.3 55.4,53.1 55.4,49.6 55.1,49.3 54.6,49.3 ; C21.2 v1(53.1,54.5) 53.1,55.2 53.4,55.5 Q2.3 ; OLED1.28 53.55,49.55 53.8,49.3 54.6,49.3 ; OLED1.30 54.55,49.35 54.6,49.3 ; C34.2 55.15,78.7 U2.8 55.15,76.95 v1(55.7,76.4) v1(56.9,75.2) ; U2.17 U2.18 55.65,73.95 v1(55.7,74) v1(56.9,75.2) ; C35.2 56.8,69.6 v1(57.1,69.9) ; C25.2 v1(57.9,65.3) ; C30.2 59.6,67 v1(59.8,66.8) ; v1(57.9,63.4) 58.6,63.4 58.7,63.3 C23.2 v1(58.7,61.7) 58.7,60.625 58.225,60.15 ; v1@59.1,69.779 v1(59.1,69.8) ; U2.30 U2.33@57.65,75.95 ; U2.31 58.15,76.45 v1(58.1,76.4) U2.33@57.65,75.95 ; C33.2 61.225,78.8 v1(61.325,78.7) 61.9,78.7 62.2,78.4 62.2,77.7 62.7,77.2 Y3.4 63.3,77.2 63.6,77.2 63.85,77.45 C42.2 ; Y3.2 61,74.1 61.65,73.45 ; v1(61.4,62.3) 61.4,61.1 v1(61.5,61) ; v1(61.4,63.5) v1(61.4,64.7) ; v1(61.5,59.9) 62.3,59.1 v1(62.3,59) ; v1(62.5,71.2) 61.6,71.2 v1(61.5,71.3) 61.306,71.494 61.127,71.494 60.994,71.627 58.634,71.627 v1(58.22,72.041) 58.15,72.111 U2.23 58.15,73.95 v1(58.1,74) v1(56.9,75.2) ; C28.1 62.35,72.8 R21.1 61.85,73.25 61.65,73.45 ; v1(62.9,43.4) 64.754,45.254 64.754,58.746 v1(64.5,59) ; v1(64,74) C41.1 61.65,73.45 ; v1(56.9,75.2) U2.33@57.65,75.95
  Top Layer w0.5: v1(32.9,75.65) 31.85,75.65 31.8,75.7 ; 32.9,77.4 32.2,77.4 31.8,77 31.8,75.7 ; v1(33.9,72.3) 33.225,72.975 C24.2 31.875,72.975 31.8,72.9 31.8,75.7
  Bottom Layer w0.152: v1@48.3,66.1 v1(48.3,66) 48.3,64.8 49.6,63.5 v1(50.8,63.5)
  Bottom Layer w0.254: J1.5@29.2,65 30.7,65 ; 30.5,54.8 30.55,54.75 R11.2 ; R8.1 32.65,44.35 32.7,44.4 ; v1(32.7,58.2) v1(35.3,58.2) ; v1(34.4,64.7) 35,65.3 35,66.6 37.8,66.6 38.1,66.9 ; v1(35.3,60.5) 35.3,60.4 v1(37.1,58.6) ; 39.4,45.7 v1(39.4,50.4) 39.4,53.375 v1(39.7,53.675) 39.7,56.1 v1(39.5,56.3) ; v1(39.7,62.6) v1@39.7,62.7 ; v1(40.4,70.4) 40.4,68.5 41.2,67.7 41.2,66.6 ; R12.2 40.75,78.5 v1(43.8,78.5) v1(45.05,78.5) 45.05,78.35 46,77.4 48.2,77.4 v1(49,78.2) 49.574,77.626 v1(50.425,77.626) 52.274,77.626 v1(52.5,77.4) 52.65,77.55 R5.2 ; 54,69.6 56.4,69.6 56.6,69.8 ; v1(58.7,61.7) 58.7,59 v1(62.3,59) v1(64.5,59) 64.5,54.5 63.95,53.95 R10.2 ; v1(59.8,66.8) 61.4,65.2 v1(61.4,64.7) ; v1(61.4,62.3) v1(61.4,63.5) ; v1(61.5,59.9) v1(61.5,61) ; R7.1 62.8,43.3 v1(62.9,43.4) ; 63.2,71.3 64.2,71.3 64.3,71.2
  Bottom Layer w0.5: J1.5@32,62.7 30.7,62.7 ; v1(32.7,58.2) 32.3,57.8 J1.5@29.2,57.8 ; v1(32.9,75.65) 31.85,75.65 31.6,75.4 31.6,71.507 30.7,70.607 30.7,68.8 ; v1(34,70.3) 34,69 34.2,68.8 32.2,68.8 30.7,68.8 ; v1(34.45,45) 34.45,44.45 34.4,44.4 ; v1(36.1,68.9) 36.3,68.7 37.8,68.7 38.1,68.4 38.1,66.9 38.1,66 38.5,65.6 39.8,65.6 40.8,66.6 41.2,66.6 42.5,66.6 43.5,65.6 43.5,63 44.3,62.2 48.8,62.2 ; v1(38.6,74) 38.6,75.1 39.1,75.6 41,75.6 43,73.6 45.5,73.6 46.8,72.3 v1(46.8,72.1) 46.9,72.2 v1(48.7,72.2) ; v1@41.3,58.8 41.6,59.1 v1(45.5,59.1) 45.7,59.3 v1(49.3,59.3) 48.8,59.8 48.8,62.2 ; 47.5,45.8 v1(47.5,52.6) ; v1(50.8,63.5) 50.8,62.2 ; v1(53.1,54.5) 51.3,52.7 51.3,47.7 v1(50.2,46.6) 49.3,45.7 39.4,45.7 37,45.7 35.7,44.4 34.4,44.4 ; v1(57.9,65.3) v1(57.9,63.4) 57.9,62.9 57.7,62.7 57.7,62.2 ; v1(58.7,61.7) 58.2,61.7 57.7,62.2 ; J1.5@29.2,57.8 30.5,56.5 30.5,54.8 30.5,53.2 31.6,52.1 31.6,52 31.4,52.2 31.4,50.105 31.172,49.877 30.502,49.877 30.007,49.382 30.007,47.193 31.243,45.957 31.243,45.852 31.6,45.495 31.6,45 32.2,44.4 32.7,44.4 34.4,44.4 ; J1.5@29.2,57.8 28.6,58.4 28.6,61.7 29.6,62.7 30.7,62.7 ; 30.7,62.7 30.7,65 30.7,68.8 ; 48.8,62.2 50.8,62.2 ; 50.8,62.2 51.1,62.2 51.4,61.9 57.7,61.9 57.7,62.2
  other v1: 34.6,50.1 33.7,52.5 37.6,53.7 41.3,58.6 29.5,64.7 60.9,65.85 54.5,67.3 32,68.55 55.9,69.8 63.6,71.2 59.3,72.8 56.9,74 55.7,75.2 58.1,75.2 56.9,76.4
INTA: U1.28 U5.8 | length 8.7
  Top Layer w0.254: U5.8 42.5,73.8 42.8,73.5 42.8,72.843 v1(42.843,72.8) ; U1.28 45.1,69.6 45.2,69.7 45.2,71.2 v1(45.187,71.213)
  Bottom Layer w0.152: v1(42.843,72.8) 42.843,71.357 43.3,70.9 44.874,70.9 v1(45.187,71.213) v1@44.913,71.213
INTM: U1.27 U4.15 | length 27.2
  Top Layer w0.152: U1.27 45.6,70.1 45.6,70.892 45.973,71.265 v1(45.973,71.315)
  Top Layer w0.254: v1(48.403,75.903) 48.906,75.4 U4.15
  Bottom Layer w0.152: v1(45.973,71.315) 45.973,71.073 45.5,70.6 43.2,70.6 41.957,71.843 41.957,73.398 40.979,74.376 39.906,74.376 39.01,73.481 38.385,73.481 38.081,73.785 38.081,75.184 38.923,76.026 48.28,76.026 v1(48.403,75.903)
IREF: OLED1.22 R16.1 | length 2.3
  Top Layer w0.254: OLED1.22 50.55,50.946 50.806,51.202 51.502,51.202 51.7,51.4 R16.1
ISET1: R27.1 U7.12 | length 1.7
  Top Layer w0.254: R27.1 33.05,74 U7.12
ISET2: R26.1 U7.13 | length 1.5
  Top Layer w0.254: v1(34.1,73.2) 34.2,73.3 34.686,73.3 35,73.614 U7.13
LED1: LED1.1 U1.6 | length 34.8
  Top Layer w0.254: U1.6 53.9,61.7 54.5,61.1 v1(54.7,61.1) ; v1(58.3,43.3) 59.4,44.4 62.5,44.4 63.8,45.7 63.8,47.3 64.4,47.9 64.4,57.7 64.1,58 v1(63,58)
  Bottom Layer w0.254: v1(54.7,61.1) 55.5,61.1 55.8,60.8 55.8,57.9 56.2,57.5 58,57.5 58.5,58 v1(63,58) ; LED1.1 v1(58.3,43.3)
LED2: LED2.1 U1.2 | length 42.9
  Top Layer w0.254: v1@51.8,59.7 U1.2
  Bottom Layer w0.254: LED2.1 36.95,44.35 37.6,45 58.1,45 59.9,46.8 59.9,51 57.483,53.418 56.182,53.418 53.847,55.753 53.847,57.052 52.03,58.87 52.03,59.07 v1(51.6,59.5)
MCLR: C1.1 R4.2 R6.1 TP7.1 | length 10.3
  Top Layer w0.254: v1(50.8,58.4) 51,58.2 55.2,58.2 55.7,58.7 R6.1 55.7,60.8 55.9,61 57,61 C1.1 R4.2
NetC14_1: C14.1 U4.12 | length 5
  Top Layer w0.152: U4.12 49.906,77.044 49.906,78.806 50.2,79.1 52,79.1 52.25,78.85 C14.1@52.25,78.2
NetC14_2: C14.2 U4.8 | length 2.6
  Top Layer w0.254: U4.8 52.4,76.4 53.1,77.1 53.1,77.9 53.4,78.2
NetC15_1: C15.1 U4.10 | length 0.5
  Top Layer w0.254: U4.10 50.925,77.325 51.1,77.5
NetC21_1: C21.1 OLED1.26 | length 1.7
  Top Layer w0.254: OLED1.26 52.55,51.275 C21.1@53.1,51.825
NetC29_1: C29.1 L2.2 | length 0.7
  Top Layer w0.254: 60.55,70.2 L2.2
NetC38_2: C38.2 D4.1 M1.2 Q2.1 | length 7.6
  Top Layer w0.254: D4.1@57.1,52.85 57.1,54.375 Q2.1 59.15,54.55 59.5,54.9 M1.2 60.05,56.65 C38.2
NetC41_2: C41.2 U2.27 Y3.3 | length 6.2
  Top Layer w0.152: U2.27 59.95,74.45 60.224,74.724 60.224,75.173 60.327,75.276 62.7,75.276 ; Y3.3 62.7,75.276 ; C41.2@64,74.95 63.726,75.224 63.376,75.224 63.324,75.276 62.7,75.276
NetC42_1: C42.1 U2.28 Y3.1 | length 6.2
  Top Layer w0.152: U2.28 59.85,74.95 59.971,75.071 59.971,75.278 60.222,75.529 61,75.529 ; Y3.1 61,75.529 ; C42.1 63.726,75.576 63.348,75.576 63.3,75.529 61,75.529
NetD2_1: D2.1 R14.1 | length 1.6
  Top Layer w0.254: D2.1 42.2,54.15 R14.1
NetD2_2: D2.2 D3.1 | length 2.2
  Top Layer w0.254: D2.2@39.95,54.7 40.2,54.7 41.5,56 D3.1
NetEPWR_1: EPWR.1 U7.5 | length 7.9
  Top Layer w0.152: U7.5 36.5,77.926 36.601,78.027 36.601,79.426 36.851,79.676 39.455,79.676 v1(39.752,79.379)
  Bottom Layer w0.254: v1(39.752,79.379) 39.752,77.248 EPWR.1
NetLED1_2: LED1.2 R7.2 | length 1.1
  Bottom Layer w0.254: LED1.2 R7.2
NetLED2_2: LED2.2 R8.2 | length 1.1
  Bottom Layer w0.254: R8.2 LED2.2
NetR6_2: R6.2 U1.7 | length 3.2
  Top Layer w0.254: U1.7 54.001,62.2 54.451,61.75 R6.2 R6.2@55.65,61.7
NetRXD_1: RXD.1 U2.10 | length 3.6
  Top Layer w0.254: v1(53.5,76.319) 53.631,76.45 U2.10
  Bottom Layer w0.254: v1(53.5,76.319) 53.6,76.419 53.6,77.9 RXD.1
NetTXD_1: TXD.1 U2.7 | length 0.9
  Top Layer w0.254: U2.7 55.65,78.307 v1(55.843,78.5)
OL_CS: OLED1.19 U1.63 | length 14
  Top Layer w0.254: v1(48.7,48.9) 49.05,49.25 OLED1.19 ; v1(48.8,58.5) 49.9,58.5 50.1,58.3 U1.63
  Bottom Layer w0.254: v1(48.7,48.9) 48.7,49.5 49,49.8 49,58.3 v1(48.8,58.5)
OL_D0: OLED1.14 U1.55 | length 7
  Top Layer w0.254: U1.55 46.1,54.302 46.258,54.144 ; 46.258,54.143 46.55,53.851 OLED1.14
OL_D1: OLED1.13 U1.54 | length 7
  Top Layer w0.254: U1.54 45.6,55.8 45.612,55.788 45.612,54.289 45.904,53.997 ; 45.904,53.996 46.05,53.85 OLED1.13
OL_D2: OLED1.12 U1.53 | length 7
  Top Layer w0.254: U1.53 45.1,54.301 45.258,54.143 ; 45.258,54.143 45.55,53.851 OLED1.12
OL_D3: OLED1.11 U1.52 | length 7
  Top Layer w0.254: U1.52 44.6,54.301 44.904,53.997 45.05,53.85 OLED1.11
OL_D4: OLED1.10 U1.51 | length 7
  Top Layer w0.254: U1.51 44.1,55.8 44.1,54.3 44.55,53.85 OLED1.10
OL_D5: OLED1.9 U1.50 | length 7
  Top Layer w0.254: U1.50 43.6,55.8 43.6,54.201 44.05,53.751 OLED1.9
OL_D6: OLED1.8 U1.49 | length 7
  Top Layer w0.254: U1.49 43.1,55.8 43.1,54.201 43.538,53.763 43.538,50.337 OLED1.8
OL_D7: OLED1.7 U1.46 | length 11.5
  Top Layer w0.254: U1.46 42.1,60.2 42.6,59.7 42.6,54.2 43.05,53.75 OLED1.7
OL_DC: OLED1.20 U1.62 | length 10.9
  Top Layer w0.254: v1(49.4,48.4) 49.55,48.55 OLED1.20 ; U1.62 49.6,56 v1(49.8,55.8)
  Bottom Layer w0.254: v1(49.4,48.4) 49.4,49.3 49.8,49.7 v1(49.8,55.8)
OL_E: OLED1.15 U1.60 | length 9.9
  Top Layer w0.254: OLED1.15 47.05,51.15 47.498,51.598 49.619,51.598 49.827,51.806 49.827,54.172 49.572,54.427 49.174,54.427 48.6,55.001 U1.60
OL_RESET: OLED1.21 U1.64 | length 10.1
  Top Layer w0.254: OLED1.21 50.05,49.15 v1(50.3,48.9) ; U1.64 50.6,56.129 v1(50.929,55.8)
  Bottom Layer w0.254: v1(50.3,48.9) 50.3,53.8 50.929,54.429 v1(50.929,55.8)
OL_RW: OLED1.16 U1.61 | length 9.6
  Top Layer w0.254: OLED1.16 47.55,50.946 47.848,51.244 49.766,51.244 50.181,51.659 50.181,54.319 49.677,54.823 49.356,54.823 49.1,55.079 49.1,55.8 U1.61
OL_SHDN: R23.1 U1.59 U6.4 | length 17.7
  Top Layer w0.254: U6.4 36.45,52.5 R23.1 37.65,52.85 v1(37.7,52.9) ; v1(47.7,58.3) 48.1,57.9 U1.59
  Bottom Layer w0.254: v1(37.7,52.9) 38.6,53.8 38.6,56.3 39.9,57.6 46.3,57.6 47,58.3 v1(47.7,58.3)
OSCI: C7.1 U1.39 Y1.1 | length 7.6
  Top Layer w0.254: C7.1@35.025,63.7 U1.39 ; 37.15,63.75 Y1.1
OSCO: C8.1 U1.40 Y1.2 | length 7.5
  Top Layer w0.254: C8.1@34.925,63.2 U1.40@40.594,63.2 ; Y1.2 37.15,63.15
PEIZO: TP11.1 U1.44 | length 13
  Top Layer w0.254: U1.44@41.4,61.2 41.9,61.2 42,61.3 43.4,61.3 v1(43.8,60.9)
  Bottom Layer w0.254: TP11.1 36.1,56.3 39.4,59.6 42.5,59.6 v1(43.8,60.9)
PGC: TP19.1 U1.17 U2.14 | length 13.6
  Top Layer w0.152: U1.17 50.6,69.8 ; v1(51.4,69.8) 50.6,69.8 ; U2.14 53.95,74.45 53.805,74.305 53.805,73.305 52.6,72.1 51.328,72.1 51.128,71.9 51.128,71.328 50.6,70.8 50.6,69.8
  Bottom Layer w0.254: v1(50.8,66.04) 52.1,67.34 52.1,69.2 v1@51.5,69.8
PGD: TP20.1 U1.18 U2.13 | length 11.7
  Top Layer w0.152: U1.18 50.1,70.7 50.876,71.476 50.876,72.276 51.1,72.5 52.6,72.5 53.552,73.452 53.552,74.752 53.75,74.95 U2.13
  Top Layer w0.254: U1.18 50.1,68.079 50.379,67.8 51.1,67.8 v1(51.5,68.2)
  Bottom Layer w0.254: v1(51.5,68.2) v1@51.6,68.3
PW_CE: R19.2 U1.33 U7.15 | length 11.1
  Top Layer w0.152: U7.15 36,73.4 36.181,73.219 36.181,71.385 36.766,70.8 v1(37,70.8)
  Top Layer w0.254: R19.2 39.85,66.7 U1.33
  Bottom Layer w0.254: v1(37,70.8) 38.4,70.8 39.3,69.9 v1(39.3,67.1)
PW_FB: C36.2 C37.1 R17.2 R18.1 U7.2 | length 5.5
  Top Layer w0.254: U7.2 39.3,77.4 39.6,77.1 R18.1 ; C36.2 R17.2 R18.1 ; C37.1 R18.1
PW_PG: U7.14
PW_SW: L5.1 U7.19 | length 2.3
  Top Layer w0.254: U7.19 38,71.75 L5.1@38.05,71.7
RD9: RD9.1 U1.43 | length 5.1
  Top Layer w0.254: U1.43 44.98,61.7 v1(45.72,60.96)
REFCLK: OSC.1 U1.30 | length 10.6
  Top Layer w0.254: U1.30 44.1,69.6 44,69.7 44,71.6 v1(44.1,71.7)
  Bottom Layer w0.254: v1(44.1,71.7) 44.1,72.1 44.2,72.2 45.9,72.2 46.2,71.9 46.2,71.894 47.194,70.9 OSC.1
RESET: U1.24 U2.19 | length 14.9
  Top Layer w0.152: U1.24 47.1,67.5 47.772,66.828 49.384,66.828 49.8,67.244 51.707,67.244 52.852,68.389 52.852,71.348 52.85,71.35 53.503,72.003 55.665,72.003 56.15,72.489 U2.19
RTCC: RTCC.1 U1.42 | length 5.3
  Top Layer w0.254: U1.42 44.4,62.2 v1(45.7,63.5)
SCK: U1.22 U2.11 | length 12.8
  Top Layer w0.152: U1.22 48.1,71.2 47.928,71.372 47.928,72.735 48.394,73.2 52.5,73.2 53,73.7 53,75.4 53.4,75.8 54.25,75.8 U2.11
SCL1: SCL.1 U1.32 U4.1 U5.14 | length 18.3
  Top Layer w0.254: U1.32 43.1,68.001 43.751,67.35 44.7,66.4 45.1,66 v1(45.7,66) ; U1.32@43.1,68.901 43.1,72.201 44.672,73.773 48,73.773 ; U5.14 47.7,75.8 48,75.5 48,73.773 ; U4.1 49.423,73.773 48,73.773
  Bottom Layer w0.254: v1(45.7,66) 45.72,66.02 SCL.1
SDA1: SDA.1 U1.31 U4.16 U5.13 | length 15.8
  Top Layer w0.254: U1.31 43.6,68.079 44.072,67.607 v1(44.627,67.607) ; U1.31@43.6,69 43.6,71.1 43.53,71.17 43.53,72.13 44.6,73.2 47.194,73.2 v1(47.197,73.203) ; U5.13 47.025,74.525 v1(47.4,74.9) ; v1(48.6,74.9) U4.16
  Bottom Layer w0.254: v1(44.627,67.607) 44.993,67.607 45.72,68.334 SDA.1 ; v1(47.197,73.203) 48,74.006 48,74.9 ; v1(47.4,74.9) 48,74.9 ; v1(48.6,74.9) 48,74.9
SOSCI: C9.1 U1.47 Y2.2 | length 12
  Top Layer w0.254: C9.1@32.025,58.2 Y2.2@32.025,59.675 ; Y2.2 32.2,59.85 32.2,60.777 34.294,60.777 34.427,60.644 34.427,59.973 34.7,59.7 U1.47
SOSCO: C10.1 U1.48 Y2.1 | length 7.9
  Top Layer w0.254: Y2.1@34,59.3 38.6,59.3 38.7,59.2 U1.48@40.894,59.2 ; C10.1@35.975,58.2 35.975,59.175
STAT1: R24.2 U1.4 U7.7 | length 35.2
  Top Layer w0.152: v1@35.082,78.357 35.5,77.939 U7.7 ; v1(49.299,62.893) 50.507,62.893 51.506,61.894 51.506,60.994 51.819,60.681 U1.4@52.781,60.681
  Top Layer w0.254: v1@35.082,78.222 v1@35.082,78.357
  Bottom Layer w0.152: R24.2 35.1,77.75 v1(35.1,78.4) 35.695,78.995 37.305,78.995 37.7,78.6 37.7,77.4 37.3,77 37.3,73.495 38.071,72.724 39.324,72.724 39.915,73.315 40.219,73.619 40.665,73.619 41.2,73.084 41.2,70.3 44.6,66.9 44.6,65.4 45.2,64.8 46,64.8 47.907,62.893 v1(49.299,62.893)
STAT2: R22.2 U1.11 U7.8 | length 35.4
  Top Layer w0.152: v1(34.3,78.3) 34.414,78.3 35,77.714 U7.8 ; v1(49.995,64.64) 51.26,64.64 51.7,64.2 U1.11
  Bottom Layer w0.152: R22.2 v1(34.3,78.3) 34.3,78.8 34.748,79.248 37.452,79.248 38,78.7 38,77.2 37.552,76.752 37.552,73.599 38.176,72.976 39.219,72.976 40.115,73.872 40.77,73.872 41.452,73.189 41.452,70.448 42.5,69.4 45.1,69.4 45.4,69.7 46.7,69.7 47.9,68.5 49,68.5 49.4,68.1 49.4,65.235 v1(49.995,64.64)
SW: D1.1 L1.2 U6.1 | length 7.6
  Top Layer w0.254: L1.2@32.3,53.975 32.3,52.5 32.575,52.225 32.575,51.475 ; D1.1 32.575,51.075 32.575,51.475 ; U6.1@34.35,48.725 U6.1 34,48.925 33.7,49.225 33.7,51.1 33.325,51.475 32.575,51.475
VBAT: C27.1 R1.1 TP14.1 U7.4 U7.16 U7.17 | length 20.9
  Top Layer w0.254: U7.16 36.5,73.2 36.75,73.2 37,73.2 U7.17 ; U7.4 37,78.068
  Top Layer w0.5: v1(36.7,71.6) 36.75,71.65 36.75,73.2
  Bottom Layer w0.254: 36.8,78.268 36.792,78.26 36.792,73.065 36.8,73.057 36.8,71.7 v1(36.7,71.6) 40.2,71.6 40.5,71.9 v1@40.5,73.3
  Bottom Layer w0.5: 32.5,71 36.1,71 v1(36.7,71.6)
  other v1: 32,70.15 40.45,73.1 37.15,78.4
VBAT_SENSE: C30.1 R1.2 R3.1 U1.16 | length 20.3
  Top Layer w0.254: R1.2 R3.1 42.6,70.75 42.6,67.999 45.299,65.3 51.1,65.3 51.5,65.7 51.5,66.4 51.8,66.7 U1.16 ; U1.16@52.3,66.7 52.324,66.724 55.526,66.724 C30.1@55.55,66.7
VBUS: C26.1 J1.1 R2.2 U7.6 USB.1 | length 28.3
  Top Layer w0.254: 31.1,67.6 R2.2@32.15,67.6 ; U7.6 C26.1@36,78.525
  Top Layer w0.5: v1(29.5,60.4) 31.1,62 31.1,67.6 31.1,77.9 32.6,79.4 35.525,79.4 C26.1@35.725,79.2
  Bottom Layer w0.5: v1(29.5,60.4) 29.8,60.1 J1.1
VBUS_SENSE: R2.1 R20.2 U1.34 | length 11.9
  Top Layer w0.254: R20.2@33.75,68.9 33.75,67.6 36,67.6 36.4,68 40.1,68 40.677,67.423 41.477,67.423 42,66.9 42,66.4 41.8,66.2 U1.34
VCAP: C6.1 U1.56 | length 3.9
  Top Layer w0.254: U1.56 46.6,55.8 46.612,55.788 46.612,54.289 46.726,54.175 C6.1 C6.1@47.6,54.175
VCC: C2.1 C3.1 C4.1 C5.1 C11.1 C12.1 C13.1 C19.1 C22.1 C23.1 C24.1 C28.2 C32.1 C36.1 C38.1 C40.1 D4.2 L1.1 L5.2 M1.1 OLED1.4 OLED1.17 OLED1.18 OLED1.27 Q1.1 R4.1 R17.1 R19.1 R22.1 R23.2 R24.1 S1.2 S2.2 S3.2 S4.2 TP17.1 U1.10 U1.19 U1.26 U1.35 U1.38 U1.57 U2.1 U2.9 U2.24 U2.26 U2.29 U4.2 U4.4 U4.13 U5.1 U5.4 U5.6 U5.7 U6.5 VCC.1 | length 282.7
  Top Layer w0.152: U4.2 50.425,73.875 50.501,73.799 51.4,73.799 ; U4.4 51.425,73.824 51.4,73.799 ; U2.9 53.397,76.95 52.6,76.153 52.6,74.1 52.299,73.799 51.4,73.799 ; 59.1,78.3 59.3,78.1 59.8,78.1 60,77.9 60,75.663 59.787,75.45 U2.29 ; U2.26@59.189,73.95 U2.26 59.807,73.95 60.281,73.476 60.673,73.476 60.9,73.249 60.9,71.981
  Top Layer w0.254: VCC.1 28.7,62.5 28.4,62.2 28.4,59.9 28.9,59.4 30.623,59.4 ; 31.393,48.093 31.6,48.3 v1(32.3,48.3) ; C24.1 33,71.125 v1(33,72) ; U6.5 34.55,52.05 35.225,52.725 L1.1 35.275,54.45 R23.2 38.3,54.45 38.3,53.1 38.7,52.7 40.7,52.7 41.1,52.3 C19.1 ; 38.2,69.6 C4.1 R19.1 ; U1.38 41.794,64.2 42.064,63.93 42.536,63.93 42.97,64.364 42.97,65.536 42.506,66 42.2,66 41.9,65.7 U1.35 ; C19.1@41.1,51.65 41.55,51.2 OLED1.4 41.55,49.25 41.7,49.1 47.8,49.1 48.05,49.35 OLED1.17 OLED1.18 ; U5.7 42.5,76.075 U5.6 C13.1@42.5,78.25 ; U5.4 44.1,77.579 44.427,77.906 44.427,79.273 44.4,79.3 ; U1.26 46.1,67.5 v1(46.5,67.1) ; C12.1 v1(46.5,78.35) U5.1 48.225,77.075 48.9,76.4 U4.13 ; 47.1,58.8 47.1,55.079 47.377,54.802 48.294,54.802 48.427,54.669 48.431,54.669 49.1,54 C5.1@49.1,53.85 ; 48.2,64.07 51.13,64.07 51.5,63.7 54,63.7 55.149,63.7 C2.1@55.449,64 ; v1(48.4,67.6) 49.121,67.6 49.6,68.079 U1.19 ; U1.19@49.6,69.379 49.6,71.4 C3.1@50.1,71.9 ; 53.05,45.55 53.05,48.7 ; U2.9 54.4,79.65 ; C22.1 54.148,51.398 53.3,51.398 53.05,51.148 OLED1.27 53.05,48.7 ; C2.1 R4.1 58.675,64.25 C23.1 ; D4.2 57.1,49.5 56.3,48.7 53.05,48.7 ; U2.24 58.65,72.45 59.119,71.981 60.9,71.981 61.998,71.981 62.206,71.773 63.173,71.773 63.9,72.5 C28.2 64.727,72.5 64.727,79.273 64.373,79.627 63.2,79.627 ; U2.1 58.65,77.85 59.1,78.3 59.1,79.65 59.123,79.627 63.2,79.627 ; C38.1@61.4,57.8 C38.1 61.65,56.95 M1.1 M1.1@63.25,56.85 ; v1(63.275,78.7) 63.275,79.552 63.2,79.627
  Top Layer w0.5: L5.2@35.15,71.7 34.475,71.025 C24.1 32.9,69.6 ; L1.1 35.225,56.275 34.577,56.923 30.623,56.923 ; 39.6,69.6 38.2,69.6 32.9,69.6 ; C13.1 42.25,79.3 42.2,79.35 ; 43.1,64.7 45.1,64.7 ; C12.1 46.65,79.35 ; 47.1,58.8 48.2,59.9 48.2,61 ; v1(50.8,60.96) 50.76,61 48.2,61 ; 59.1,79.65 54.4,79.65 46.95,79.65 46.65,79.35 ; M1.1 v1(62.5,49.9) 62.5,46.9 61.1,45.5 38,45.5 37.3,44.8 37.3,44.2 36.8,43.7 31.5,43.7 31,44.2 31,47.1 31.393,47.493 31.393,48.093 31.393,49.707 30.6,50.5 30.6,56.9 30.623,56.923 ; 30.623,56.923 30.623,59.4 30.623,60.569 31.8,61.746 31.8,65.7 32.9,66.8 32.9,69.6 ; 42.2,79.35 41.65,79.35 41.6,79.3 41.6,74.3 41.3,74 40.794,74 40.787,73.993 39.643,73.993 R17.1 39.6,69.614 40.186,69.614 45.1,64.7 ; 42.2,79.35 46.65,79.35 ; 45.1,64.7 v1(47.1,64.7) 47.7,64.7 48.2,64.2 48.2,64.07 48.2,61
  Bottom Layer w0.254: v1(32.3,48.3) 32.9,47.7 S2.2 ; v1(33,72) 32.9,72.1 S1.2 32.9,74.45 R22.1 R24.1 ; v1(46.5,67.1) 46.8,67.4 47.1,67.4 ; v1(47.1,64.7) 47.1,67.4 ; v1(48.4,67.6) 48.2,67.4 47.1,67.4 ; S3.2 v1(62.5,49.9) ; S4.2 63,77.5 63.275,77.775 v1(63.275,78.7)
VCOMH: C17.1 OLED1.3 | length 2.3
  Top Layer w0.254: C17.1 40.223,51.202 40.794,51.202 41.05,50.946 OLED1.3
VDD_PA: C35.1 C39.1 L4.2 U2.20 | length 6.6
  Top Layer w0.254: L4.2@54,70.75 L4.2 ; C39.1 54.35,68.5 C35.1 54.35,70.7 L4.2 ; U2.20 56.65,72.05 56.3,71.7 54.8,71.7 54.15,71.05 L4.2
VMOTOR: Q2.2 U1.3 | length 6.3
  Top Layer w0.254: U1.3 v1(54.3,60.2)
  Bottom Layer w0.254: v1(54.3,60.2) 54.67,59.83 54.67,58.529 56.399,56.8 v1(56.9,56.8)
VSL: OLED1.5 R14.2 | length 1.4
  Top Layer w0.254: OLED1.5 42.05,51.4 R14.2@42.3,51.65
pads on no net: ANT1.2 J1.4 OLED1.6 OLED1.23 OLED1.24 OLED1.25 OLED1.29 OLED1.31 OLED1.32 Q1.2 S1.3 S2.3 S3.3 S4.3 U1.5 U1.58 U2.4 U2.5 U2.6 U2.15 U2.32 U4.3 U4.5 U4.6 U4.7 U4.14 U5.3 U5.9 U5.10 U5.11 U5.12 U7.1 U7.10 U7.11

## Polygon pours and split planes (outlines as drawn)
GND on Bottom Layer "Bottom Layer-No Net" (solid, pour order 14): 29.4,80.4 65.2,80.4 65.2,42.3 56.8,42.3 56.6,42.5 56.5,42.6 56.5,44.1 38.3,44.1 38.2,44.2 38.1,44.1 38.1,42.5 29.4,42.5 29.3,42.6 29.2,42.7 29.2,55.9 29.2,56.1 28.7,56.6 28.5,56.8 27.9,56.8 27.9,66.1 27.8,66.2 28.4,66.2 28.5,66.2 29.1,66.8 29.3,67 29.3,80.3
GND on Top Layer "Bottom Layer-No Net" (solid, remove dead copper, pour order 16): 29.4,80.4 65.1,80.4 65.3,80.2 65.3,42.4 56.9,42.4 56.8,42.3 56.6,42.5 56.6,44 38.2,44 38.1,43.9 38.1,42.4 29.4,42.4 29.3,42.5 29.3,56.3 28.9,56.7 28,56.7 28,65.9 27.8,66.1 28,66.3 28.5,66.3 28.8,66.3 29.4,66.9

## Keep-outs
Keep-Out Layer:
  the board outline again, w0.254

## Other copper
Top Layer:
  pour cut-out: 49,77.2 49,73.9 52.4,73.9 52.4,77.2
  pour cut-out: 65.15,59.5 62.45,59.5 cw(c62.45,60) 61.95,60 61.95,70.5 cw(c62.45,70.5) 62.45,71 65.15,71
Bottom Layer:
  pour cut-out: 49,77.2 49,73.9 52.4,73.9 52.4,77.2
  pour cut-out: 65.15,59.5 62.45,59.5 cw(c62.45,60) 61.95,60 61.95,70.5 cw(c62.45,70.5) 62.45,71 65.15,71

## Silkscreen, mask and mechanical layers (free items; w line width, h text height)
Top Overlay:
  circle w0.254: c30.6,43.7 r0.424
  lines w0.254: 30.3,44.8 30.6,45.1 ; 30.9,44.8 30.6,45.1 ; 31.7,43.4 32,43.7 ; 31.7,44 32,43.7 ; 31.7,60.8 31.7,66.4 34.1,66.4 34.1,60.8 ; 37.4,53.3 37.6,53.3 ; 38.3,44.8 47.3,44.8 56.3,44.8 ; 65.1,59.5 62.5,59.5 cw(c62.5,60) 62,60 62,70.6 cw(c62.4,70.6) 62.4,71 65.1,71 ; 30.6,45.1 30.6,43.7 32,43.7
  text "Y" at 30.4,45.5 h0.7
  text "X" at 32.4,43.4 h0.7
Bottom Overlay:
  lines w0.254: 65.1,59.5 62.5,59.5 cw(c62.5,60) 62,60 62,70.6 cw(c62.4,70.6) 62.4,71 65.1,71 ; 36,44.4 36,79.4 61,79.4 61,44.4 36,44.4
  text "OLED Watch" at 50.5,50.5 h1.2
  text "Rev2" at 42.1,49.1 h0.8
  text "Jared Sanson 2013" at 50.6,46.8 h0.8
Top Solder:
  lines w1.2: 27.9,56.725 28.03,56.725 cw(c28.03,55.455) 29.3,55.455 29.3,42.325 37.9,42.325 ccw(c37.9,42.625) 38.2,42.625 38.2,43.825 cw(c38.5,43.825) 38.5,44.125 56.2,44.125 cw(c56.2,43.825) 56.5,43.825 56.5,42.725 ccw(c56.9,42.725) 56.9,42.325 65.3,42.325 65.3,80.425 29.3,80.425 29.3,67.395 cw(c28.03,67.395) 28.03,66.125 27.9,66.125 27.9,56.725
